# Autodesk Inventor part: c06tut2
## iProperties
Shininess: 77.0
Length Units: 11269
Angle Units: 11279
Time Units: 11290
Mass Units: 11283
Length Display Precision: 3
Angle Display Precision: 2
Created: 2001-12
Part Number: c06tut2
Document SubType Name: Modeling
Designer: Renu Muthoo
Density: 1 g/cm^3
Density: 0.0
Volumn: 0.0
Area: 0.0
PropertySet Name: Model Information
Control State: 0
Master: False
Checked Out: False
Author: Renu Muthoo
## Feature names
1. Extrusion1
2. Hole1
3. Extrusion2
4. Extrusion3
5. Extrusion4
6. Extrusion5
7. Hole2
8. Hole3
9. Hole4
